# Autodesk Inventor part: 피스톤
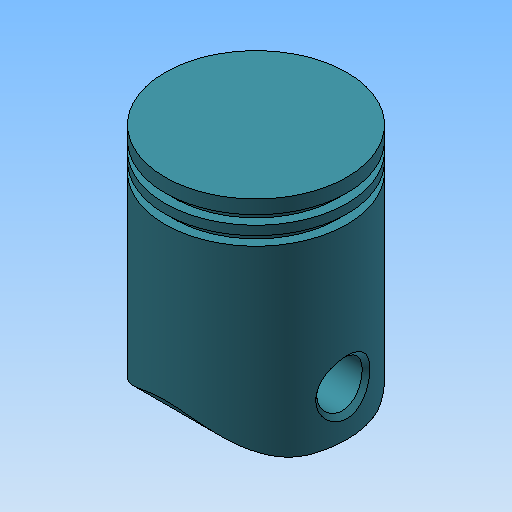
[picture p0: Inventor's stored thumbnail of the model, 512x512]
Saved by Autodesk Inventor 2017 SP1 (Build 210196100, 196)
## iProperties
Created: 2017-05
Part Number: 피스톤
Material: 알루미늄 6061
Document SubType Name: Modeling
Designer: mduedu
Density: 2.71 g/cm^3
Mass: 87.6982 g
Surface Area: 150.47 cm^2
Volume: 32.361 cm^3
Appearance: 커뎃 파란색
Author: mduedu
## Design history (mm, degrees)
sketch "스케치1"
  geometry: L1 (0, 0)-(20, 0); L2 (20, -50)-(15, -50); L3 (15, -50)-(15, -5); L4 (15, -5)-(0, -5); L5 (0, -5)-(0, 0); L6 (20, -3)-(18, -3); L7 (18, -3)-(18, -5); L8 (18, -5)-(20, -5); L9 (20, -7)-(18, -7); L10 (18, -7)-(18, -9); L11 (18, -9)-(20, -9); L12 (20, 0)-(20, -3); L13 (20, -5)-(20, -7); L14 (20, -9)-(20, -50); L15 (0, -60)-(0, 10) reference
  constraints: 28 end point, 10 parallel, 5 perpendicular, 4 collinear, 3 horizontal
  dimensions: "d0" = 20 distance of L1.start L1.end; "d1" = 2 distance of L6.start L6.end; "d2" = 2 distance of L6.end L7.end; "d3" = 2 distance of L8.end L9.start; "d4" = 3 distance of L1.end L6.start; "d5" = 5 distance of L2.start L2.end; "d6" = 50 distance between parallel lines of L1 L2; "d7" = 5 distance of L4.end L1.start
revolve "회전1" sketch "스케치1" stored, may be unused: angle "d8" = 90 deg
fillet "모깎기1" dims "d9" = 1
sketch "스케치2"
  geometry: L1 (-50, 15)-(-50, -15) reference; C1 r 10 at (-40, 0); 1 further point
  constraints: 1 centre point, 1 horizontal alignment
  dimensions: "d10" = 20 diameter of C1; "d11" = 10 distance from line of C1.centre L1
extrude "돌출1" join sketch "스케치2" stored distance "d12" = 10; taper "d13" = 0 deg
sketch "스케치3"
  geometry: L1 (0, -20)-(-3, -20) reference; L2 (-3, -20)-(-3, -18) reference; L3 (-3, -18)-(-5, -18) reference; L4 (-5, -18)-(-5, -20) reference; L5 (-5, -20)-(-7, -20) reference; L6 (-7, -20)-(-7, -18) reference; L7 (-7, -18)-(-9, -18) reference; L8 (-9, -18)-(-9, -20) reference; L9 (-9, -20)-(-50, -20) reference; L10 (-50, -20)-(-50, -15) reference; L11 (-50, -15)-(-6, -15) reference; L12 (-5, -14)-(-5, 14) reference; L13 (-6, 15)-(-50, 15) reference; L14 (-50, 15)-(-50, 20) reference; L15 (-50, 20)-(-9, 20) reference; L16 (-9, 20)-(-9, 18) reference; L17 (-9, 18)-(-7, 18) reference; L18 (-7, 18)-(-7, 20) reference; L19 (-7, 20)-(-5, 20) reference; L20 (-5, 20)-(-5, 18) reference; L21 (-5, 18)-(-3, 18) reference; L22 (-3, 18)-(-3, 20) reference; L23 (-3, 20)-(0, 20) reference; L24 (0, 20)-(0, -20) reference; C1 r 10 at (-40, 0) reference; C2 r 5 at (-40, 0); A1 r 1 centre (-6, -14) between (-6, -15) and (-5, -14) reference; A2 r 1 centre (-6, 14) between (-5, 14) and (-6, 15) reference; 1 further point
  constraints: 1 centre point, 1 coincident
  dimensions: "d15" = 10 diameter of C2
extrude "돌출2" cut sketch "스케치3" stored distance "d16" = 10; taper "d17" = 0 deg
sketch "스케치4"
  geometry: L1 (15, -50)-(-15, -50) reference; L2 (-15, -50)-(-20, -50) reference; L3 (-20, -50)-(-20, -45) reference; L4 (20, -45)-(20, -50) reference; L5 (20, -50)-(15, -50) reference; L6 (-15, -30)-(15, -30) reference; L7 (15, -30)-(15, -6) reference; L8 (14, -5)-(-14, -5) reference; L9 (-15, -6)-(-15, -30) reference; L10 (-20, -3)-(-20, 0) reference; L11 (-20, 0)-(20, 0) reference; L12 (20, 0)-(20, -3) reference; L13 (20, -3)-(18, -3) reference; L14 (18, -3)-(18, -5) reference; L15 (18, -5)-(20, -5) reference; L16 (20, -5)-(20, -7) reference; L17 (20, -7)-(18, -7) reference; L18 (18, -7)-(18, -9) reference; L19 (18, -9)-(20, -9) reference; L20 (-20, -9)-(-18, -9) reference; L21 (-18, -9)-(-18, -7) reference; L22 (-18, -7)-(-20, -7) reference; L23 (-20, -7)-(-20, -5) reference; L24 (-20, -5)-(-18, -5) reference; L25 (-18, -5)-(-18, -3) reference; L26 (-18, -3)-(-20, -3) reference; L27 (0, 0)-(0, -50); L28 (-5.698, -50)-(-5, -30); L29 (5.698, -50)-(5, -30); L30 (-5, -30)-(5, -30); L31 (-5.698, -50)-(5.698, -50); L32 (-20, -45)-(20, -45) reference; L33 (20, -9)-(20, -35) reference; L34 (20, -35)-(-20, -35) reference; L35 (-20, -35)-(-20, -9) reference; A1 r 1 centre (14, -6) between (15, -6) and (14, -5) reference; A2 r 1 centre (-14, -6) between (-14, -5) and (-15, -6) reference
  constraints: 10 end point, 2 point on line, 2 symmetric about line, 1 midpoint, 1 parallel, 1 perpendicular
  dimensions: "d18" = 2 deg angle of L27 L28; "d19" = 5 distance from line of L27 L28.end
extrude "돌출3" cut sketch "스케치4" stored distance "d20" = 20; taper "d21" = 0 deg
chamfer "모따기1" distance "d22" = 1; stored, may be unused: second distance "d23" = 2, angle "d24" = 45 deg
sketch "스케치5"
  geometry: L1 (-50, 0)-(-50, -15) reference; L2 (-50, 15)-(-50, 0) reference; L3 (-9, 20)-(-50, 20) reference; L4 (-50, 20)-(-50, -20) reference; L5 (-9, -20)-(-50, -20) reference; L6 (-42.483, -20)-(-50, -20); L7 (-50, -20)-(-50, -7); L8 (-42.483, 20)-(-50, 20); L9 (-50, 20)-(-50, 7); A1 r 15 centre (-35, 7) between (-42.483, 20) and (-50, 7); A2 r 15 centre (-35, -7) between (-42.483, -20) and (-50, -7); 1 further point
  constraints: 8 end point, 4 point on circle, 4 point on line, 2 centre point, 2 tangent, 1 collinear, 1 equal radius, 1 perpendicular
  dimensions: "d25" = 30 diameter of A1; "d26" = 7 vertical distance of A2.centre point (0, 0); "d27" = 7 vertical distance of point (0, 0) A1.centre (= d26)
extrude "돌출4" cut sketch "스케치5" stored distance "d28" = 20; taper "d29" = 0 deg
node "솔리드1"
node "절단 모서리 투영1"
node "절단 모서리 투영2"
